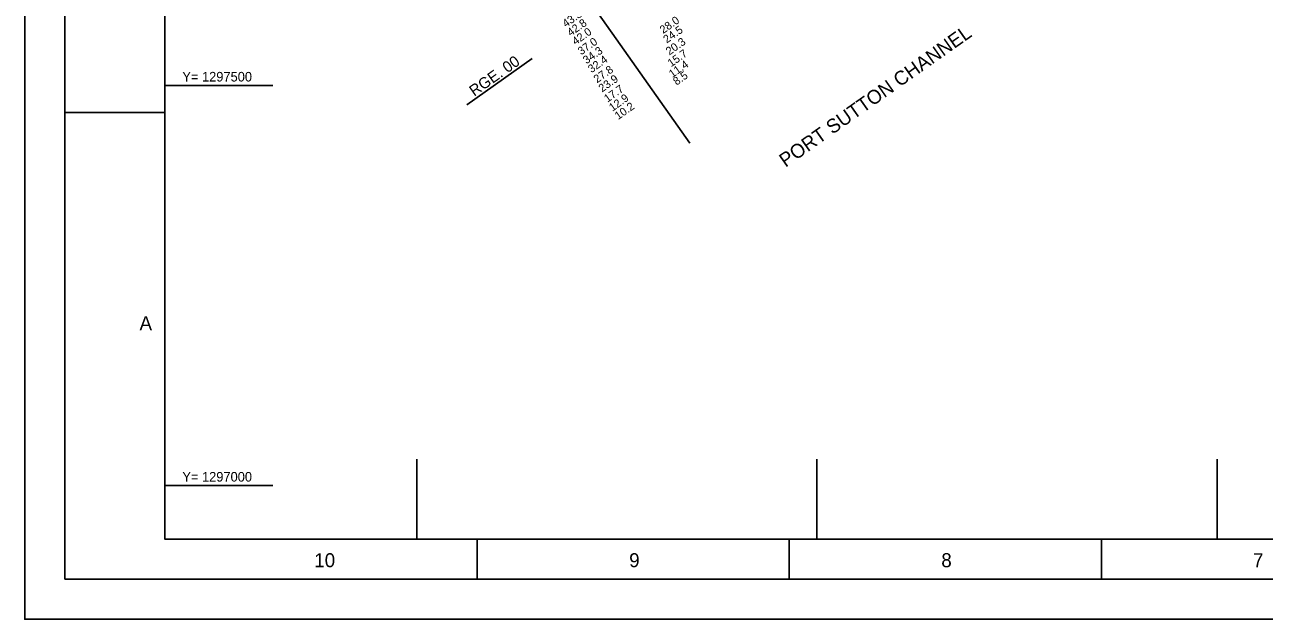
# Model space of a CAD drawing. Extents: x 515010 to 519411, y 1296833 to 1300233.
# Drawn here: x 515010 to 516559, y 1296833 to 1297576 of the extents above; entities that cross this region are included whole.
import ezdxf

# ---------------------------------------------------------------- set-up
doc = ezdxf.new("R2010")
doc.units = 0
for name, color, linetype in [('G-ANNO-NPLT', 7, 'Continuous'), ('G-ANNO-TTLB', 7, 'Continuous'), ('V-ALGN-TEXT', 7, 'Continuous'), ('V-ANNO-MATC', 7, 'Continuous'), ('V-CHAN-CNTR-IDEN', 7, 'Continuous'), ('V-TOPO-COOR-STAT', 7, 'Continuous'), ('V-TOPO-SOUN', 7, 'Continuous')]:
    doc.layers.add(name, color=color, linetype=linetype)

msp = doc.modelspace()

# ---------------------------------------------------------------- linework, layer by layer
at = {"layer": 'G-ANNO-NPLT'}
msp.add_lwpolyline([(515010.4, 1300233), (519410.4, 1300233), (519410.4, 1296833), (515010.4, 1296833)], close=True, dxfattribs=at)
msp.add_lwpolyline([(515010.4, 1296883), (515010.4, 1296833), (515060.4, 1296833)], dxfattribs=at)
at = {"layer": 'G-ANNO-TTLB'}
for p, q in [((515060.4, 1297466.3), (515185.4, 1297466.3)), ((515575.4, 1296883), (515575.4, 1296933)), ((515965.4, 1296883), (515965.4, 1296933)), ((516355.4, 1296883), (516355.4, 1296933))]:
    msp.add_line(p, q, dxfattribs=at)
for points in [[(515060.4, 1296883), (519360.4, 1296883), (519360.4, 1300183), (515060.4, 1300183)], [(519310.4, 1300133), (515185.4, 1300133), (515185.4, 1296933), (519310.4, 1296933)]]:
    msp.add_lwpolyline(points, close=True, dxfattribs=at)
at = {"layer": 'V-ALGN-TEXT'}
msp.add_line((515562.7, 1297476), (515644.4, 1297533.6), dxfattribs=at)
at = {"layer": 'V-ANNO-MATC'}
msp.add_line((515841.4, 1297427.8), (515380.6, 1298081.7), dxfattribs=at)
at = {"layer": 'V-TOPO-COOR-STAT'}
for p, q in [((515320.4, 1297500), (515185.4, 1297500)), ((515500, 1296933), (515500, 1297033)), ((516000, 1296933), (516000, 1297033)), ((516500, 1296933), (516500, 1297033)), ((515320.4, 1297000), (515185.4, 1297000))]:
    msp.add_line(p, q, dxfattribs=at)

# ---------------------------------------------------------------- texts
at = {"layer": 'G-ANNO-TTLB'}
for s, p in [('A', (515153.8, 1297194.2)), ('10', (515372.1, 1296898)), ('9', (515765.5, 1296898)), ('8', (516155.4, 1296898)), ('7', (516544.8, 1296898))]:
    msp.add_text(s, height=17.5, dxfattribs=at).set_placement(p)
at = {"layer": 'V-ALGN-TEXT'}
msp.add_text('RGE. 00', height=13.92, rotation=35.171, dxfattribs=at).set_placement((515571.9, 1297485.9))
at = {"layer": 'V-CHAN-CNTR-IDEN'}
msp.add_text('PORT SUTTON CHANNEL', height=17.52, rotation=35.171, dxfattribs=at).set_placement((515960.8, 1297397.1))
at = {"layer": 'V-TOPO-COOR-STAT'}
for s, p in [('Y= 1297500', (515207.3, 1297505)), ('Y= 1297000', (515207.3, 1297005))]:
    msp.add_text(s, height=12, dxfattribs=at).set_placement(p)
at = {"layer": 'V-TOPO-SOUN'}
for s, p in [('43.3 ', (515686.4, 1297572.1)), ('42.8 ', (515692.3, 1297561)), ('28.0 ', (515808, 1297564.3)), ('42.0 ', (515698.4, 1297550)), ('24.5 ', (515812.4, 1297552.4)), ('37.0 ', (515705.6, 1297537.6)), ('20.3 ', (515815.7, 1297537.5)), ('34.3 ', (515712.1, 1297526.4)), ('32.4 ', (515718.4, 1297515.3)), ('15.7 ', (515817.9, 1297522.7)), ('27.8 ', (515725.4, 1297502.7)), ('11.4 ', (515819.4, 1297509.2)), ('23.9 ', (515731.6, 1297491.2)), ('8.5', (515824.7, 1297499.7)), ('17.7 ', (515738.4, 1297478.4)), ('12.9 ', (515744.6, 1297467.2)), ('10.2 ', (515751.8, 1297456.8))]:
    msp.add_text(s, height=10, rotation=35.1708, dxfattribs=at).set_placement(p)

doc.saveas('drawing.dxf')
